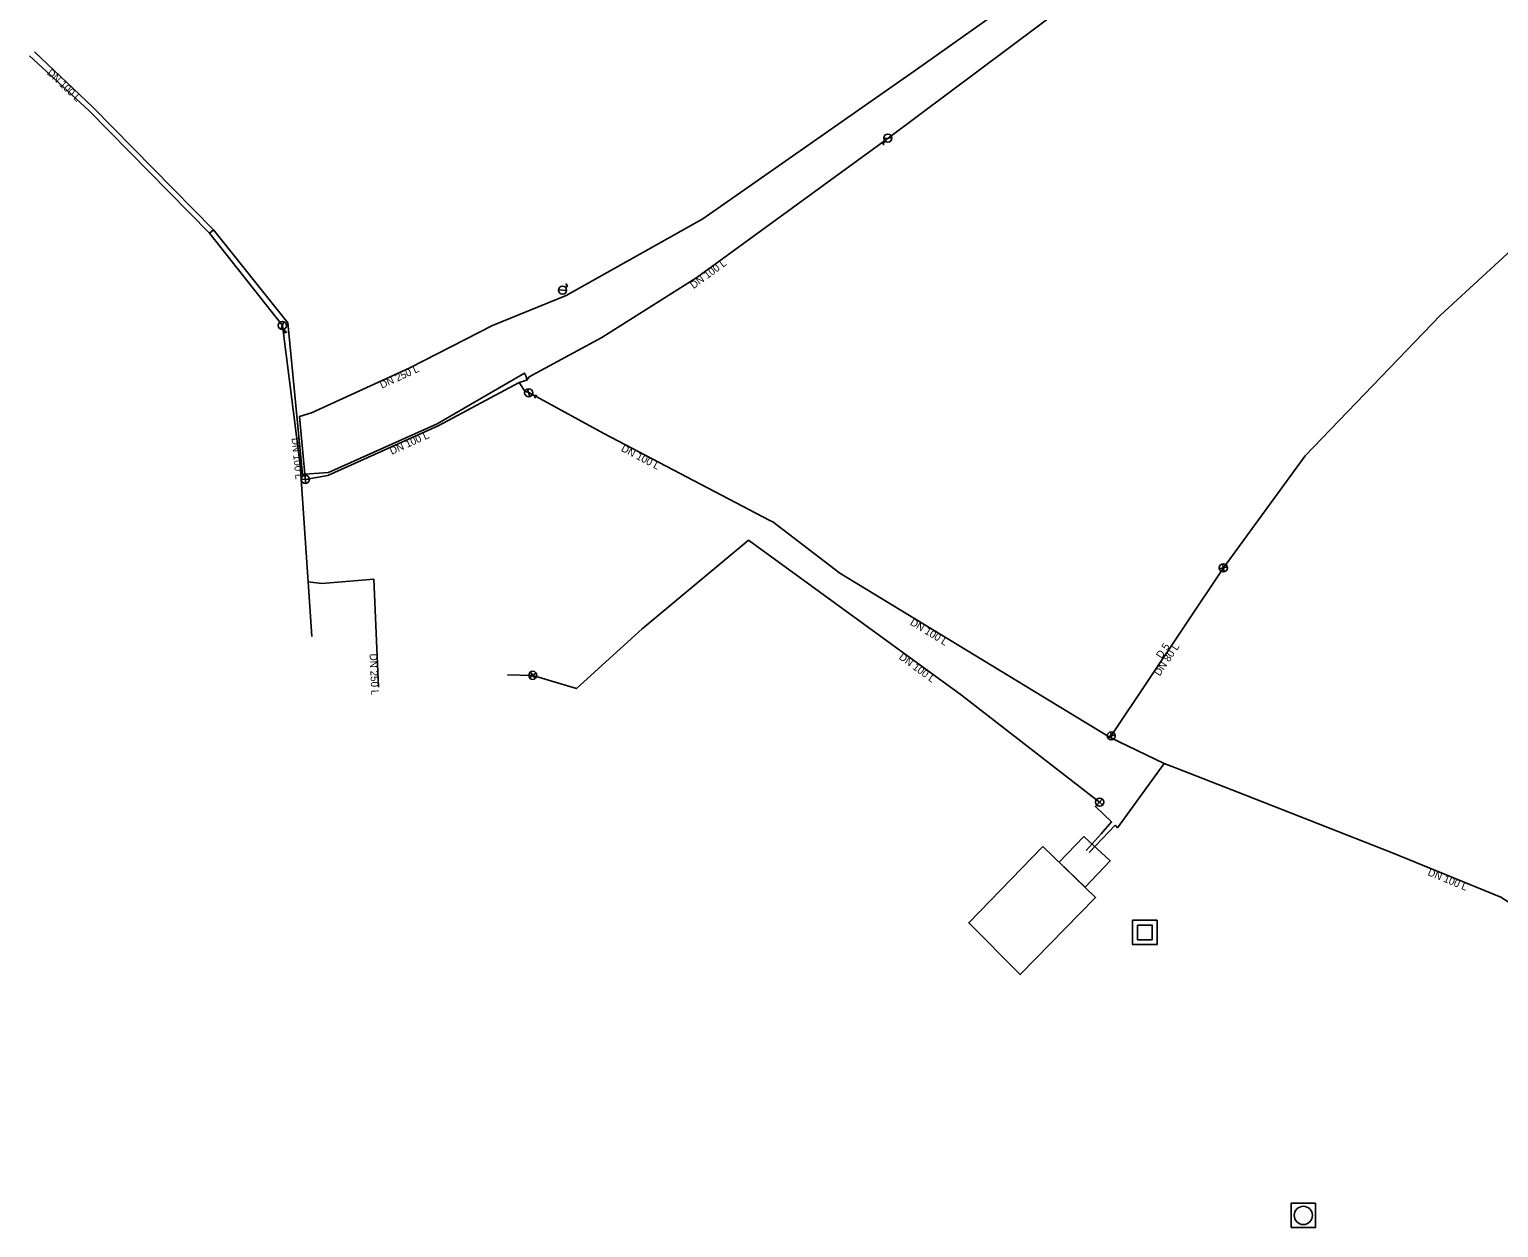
# Model space of a CAD drawing. Extents: x -600635 to -600187, y -1203951 to -1203569.
# Drawn here: x -600634.8 to -600453.9, y -1203896.1 to -1203748.5 of the extents above; entities that cross this region are included whole.
import ezdxf

# ---------------------------------------------------------------- set-up
doc = ezdxf.new("R2010")
doc.units = 0
for name, color, linetype in [('cerpaci_stanice_vod_v_majetku_nebo_provozovana', 7, 'Continuous'), ('cerpaci_stanice_vod_v_majetku_nebo_provozovana_obrys', 7, 'Continuous'), ('Default', 7, 'Continuous'), ('hydrant_v_majetku_nebo_provozovany', 7, 'Continuous'), ('popisy_rad', 7, 'Continuous'), ('rad_v_majetku', 7, 'Continuous'), ('uzaver_v_majetku_nebo_provozovany', 7, 'Continuous'), ('vodojem_v_majetku_nebo_provozovany', 7, 'Continuous'), ('vodojem_v_majetku_nebo_provozovany_obrys', 7, 'Continuous')]:
    doc.layers.add(name, color=color, linetype=linetype)

# ---------------------------------------------------------------- blocks, each defined once
blk = doc.blocks.new('MoSymbol 1')
at = {"layer": 'Default'}
blk.add_lwpolyline([(-0.00005, -0.00005), (0.00005, -0.00005), (0.00005, 0.00005), (-0.00005, 0.00005), (-0.00005, -0.00005)], dxfattribs=at)
blk.add_circle((0, 0), 0.0000375, dxfattribs=at)
blk = doc.blocks.new('MoSymbol 2')
at = {"layer": 'Default'}
for p, q in [((-0.000035, -0.000035), (0.000035, 0.000035)), ((0.000035, -0.000035), (-0.000035, 0.000035))]:
    blk.add_line(p, q, dxfattribs=at)
for radius in [0.00005, 0.0000025]:
    blk.add_circle((0, 0), radius, dxfattribs=at)
blk = doc.blocks.new('MoSymbol 3')
at = {"layer": 'Default'}
for p, q in [((-0.000036, -0.000036), (0.000036, 0.000036)), ((-0.000023, 0.000095), (0.000023, 0.000095)), ((0, 0.000095), (0, 0.00005))]:
    blk.add_line(p, q, dxfattribs=at)
blk.add_circle((0, 0), 0.00005, dxfattribs=at)
blk = doc.blocks.new('MoSymbol 4')
at = {"layer": 'Default'}
for p, q in [((-0.000036, -0.000036), (0.000036, 0.000036)), ((0.00003, -0.00008), (0.00002, -0.000085))]:
    blk.add_line(p, q, dxfattribs=at)
blk.add_lwpolyline([(0, -0.00005), (0, -0.00008), (0.00003, -0.00008), (0.00002, -0.000075)], dxfattribs=at)
blk.add_circle((0, 0), 0.00005, dxfattribs=at)
blk = doc.blocks.new('MoSymbol 6')
at = {"layer": 'Default'}
blk.add_lwpolyline([(-0.00005, 0.00005), (0.00005, 0.00005), (0.00005, -0.00005), (-0.00005, -0.00005), (-0.00005, 0.00005)], dxfattribs=at)
blk.add_lwpolyline([(-0.00003, 0.00003), (0.00003, 0.00003), (0.00003, -0.00003), (-0.00003, -0.00003)], close=True, dxfattribs=at)

msp = doc.modelspace()

# ---------------------------------------------------------------- linework, layer by layer
at = {"layer": 'cerpaci_stanice_vod_v_majetku_nebo_provozovana_obrys'}
msp.add_lwpolyline([(-600504.95, -1203847.94), (-600501.73, -1203850.94), (-600504.79, -1203854.15), (-600508, -1203851.08)], close=True, dxfattribs=at)
at = {"layer": 'rad_v_majetku'}
for p, q in [((-600612.66, -1203773.6), (-600612.16, -1203773.2)), ((-600612.66, -1203773.6), (-600603.65, -1203784.96)), ((-600573.58, -1203791.69), (-600574.49, -1203792)), ((-600601.36, -1203803.91), (-600600.85, -1203803.93)), ((-600487.77, -1203814.83), (-600501.58, -1203835.53)), ((-600600.51, -1203816.57), (-600600.05, -1203823.29)), ((-600572.83, -1203828.07), (-600575.93, -1203828)), ((-600501.58, -1203835.53), (-600501.72, -1203835.73)), ((-600501.72, -1203835.73), (-600495.04, -1203838.92))]:
    msp.add_line(p, q, dxfattribs=at)
for points in [[(-600454.25, -1203701.01), (-600472.2, -1203715.15), (-600488.66, -1203727.34), (-600496.91, -1203733.12), (-600525.43, -1203753.34), (-600551.89, -1203771.85), (-600568.7, -1203781.3)], [(-600529.07, -1203761.9), (-600506.65, -1203745.16), (-600494.67, -1203737.19), (-600466.59, -1203717.37), (-600450.01, -1203704.7)], [(-600634.84, -1203751.74), (-600627.51, -1203758.48), (-600612.66, -1203773.6)], [(-600612.16, -1203773.2), (-600627.02, -1203758.09), (-600634.21, -1203751.28)], [(-600573.58, -1203791.69), (-600573.28, -1203791.31), (-600564.33, -1203786.44), (-600552.62, -1203779.07), (-600529.07, -1203761.9)], [(-600395.74, -1203804.12), (-600404.97, -1203798.52), (-600440.98, -1203772.83), (-600445.61, -1203769.54), (-600461.03, -1203783.69), (-600477.7, -1203801.02), (-600487.77, -1203814.83)], [(-600612.16, -1203773.2), (-600603, -1203784.64), (-600601.19, -1203803.34), (-600600.9, -1203803.29), (-600597.99, -1203803.08), (-600584.6, -1203797.08), (-600575.12, -1203791.57), (-600573.86, -1203790.83), (-600573.64, -1203791.26), (-600573.58, -1203791.69)], [(-600600.85, -1203803.93), (-600600.9, -1203803.29), (-600601.58, -1203796.19), (-600600.08, -1203795.75), (-600587.99, -1203790.2), (-600577.78, -1203784.97), (-600568.7, -1203781.3)], [(-600603.65, -1203784.96), (-600601.5, -1203802.2), (-600601.36, -1203803.91)], [(-600574.49, -1203792), (-600584.47, -1203797.34), (-600598.08, -1203803.45), (-600600.85, -1203803.93)], [(-600574.49, -1203792), (-600573.82, -1203793.08), (-600573.31, -1203793.22)], [(-600543.62, -1203808.99), (-600564.07, -1203798.29), (-600573.31, -1203793.22)], [(-600601.36, -1203803.91), (-600600.52, -1203815.98), (-600600.51, -1203816.57)], [(-600501.72, -1203835.73), (-600535.01, -1203815.5), (-600543.27, -1203809.18), (-600543.62, -1203808.99)], [(-600546.27, -1203811.42), (-600546.78, -1203811.89), (-600559.37, -1203822.34)], [(-600546.27, -1203811.42), (-600520.03, -1203830.53), (-600503.01, -1203843.69)], [(-600591.84, -1203829.54), (-600592.41, -1203816.24), (-600598.81, -1203816.77), (-600600.51, -1203816.57)], [(-600559.37, -1203822.34), (-600567.46, -1203829.7), (-600572.83, -1203828.07)], [(-600495.04, -1203838.92), (-600500.79, -1203846.84), (-600501.11, -1203846.54), (-600504.31, -1203849.88)], [(-600495.04, -1203838.92), (-600493.65, -1203839.47), (-600485.04, -1203842.84)], [(-600485.04, -1203842.84), (-600467.04, -1203849.9), (-600453.61, -1203855.4), (-600438.63, -1203864.89), (-600435.58, -1203867.87)], [(-600504.66, -1203849.65), (-600502.83, -1203847.59), (-600501.54, -1203846.13), (-600503.53, -1203844.23), (-600503.01, -1203843.69)]]:
    msp.add_lwpolyline(points, dxfattribs=at)
at = {"layer": 'vodojem_v_majetku_nebo_provozovany_obrys'}
msp.add_lwpolyline([(-600510.02, -1203849.15), (-600503.5, -1203855.42), (-600512.79, -1203864.93), (-600519.12, -1203858.54)], close=True, dxfattribs=at)

# ---------------------------------------------------------------- block references
at = {"layer": 'cerpaci_stanice_vod_v_majetku_nebo_provozovana', "xscale": 29996.250468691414, "yscale": 29996.250468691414}
msp.add_blockref('MoSymbol 1', (-600477.92, -1203894.6), dxfattribs=at)
at = {"layer": 'hydrant_v_majetku_nebo_provozovany'}
for name, p, xscale, yscale, rotation in [('MoSymbol 3', (-600529.1, -1203761.89), 9998.75015623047, 9998.750156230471, 138.37882730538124), ('MoSymbol 4', (-600569.16, -1203780.62), 9998.750156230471, 9998.75015623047, 129.01940047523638), ('MoSymbol 3', (-600603.68, -1203784.98), 9998.750156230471, 9998.75015623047, -154.96493830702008), ('MoSymbol 3', (-600573.33, -1203793.26), 9998.750156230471, 9998.75015623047, -117.98322017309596)]:
    msp.add_blockref(name, p, dxfattribs=dict(at, xscale=xscale, yscale=yscale, rotation=rotation))
at = {"layer": 'uzaver_v_majetku_nebo_provozovany'}
for p, xscale, yscale, rotation in [((-600600.85, -1203803.93), 9998.750156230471, 9998.75015623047, -134.120714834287), ((-600487.77, -1203814.83), 9998.75015623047, 9998.75015623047, -124.90443168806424), ((-600572.83, -1203828.07), 9998.75015623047, 9998.750156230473, 170.91124920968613), ((-600501.58, -1203835.53), 9998.75015623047, 9998.750156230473, -124.55979820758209), ((-600503.01, -1203843.69), 9998.75015623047, 9998.750156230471, -85.73199708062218)]:
    msp.add_blockref('MoSymbol 2', p, dxfattribs=dict(at, xscale=xscale, yscale=yscale, rotation=rotation))
at = {"layer": 'vodojem_v_majetku_nebo_provozovany', "xscale": 29996.250468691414, "yscale": 29996.250468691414}
msp.add_blockref('MoSymbol 6', (-600497.44, -1203859.74), dxfattribs=at)

# ---------------------------------------------------------------- texts
at = {"layer": 'popisy_rad'}
for s, rotation, p in [('DN 100 L', 316.5884, (-600632.73, -1203753.94)), ('DN 100 L', 36.0947, (-600553.03, -1203780.5)), ('DN 250 L', 24.6653, (-600591.41, -1203792.77)), ('DN 100 L', 24.1929, (-600590.2, -1203800.91)), ('DN 100 L', 275.5146, (-600602.54, -1203798.85)), ('DN 100 L', 332.3751, (-600562.03, -1203800.39)), ('DN 100 L', 328.7108, (-600526.44, -1203821.78)), ('DN 100 L', 323.9317, (-600527.81, -1203825.99)), ('DN 80 L', 56.285, (-600495.61, -1203828.23)), ('D 5', 56.285, (-600495.38, -1203826.07)), ('DN 250 L', 272.4385, (-600592.93, -1203825.41)), ('DN 100 L', 337.7116, (-600462.67, -1203852.67))]:
    msp.add_text(s, height=0.91, rotation=rotation, dxfattribs=at).set_placement(p)

doc.saveas('drawing.dxf')
